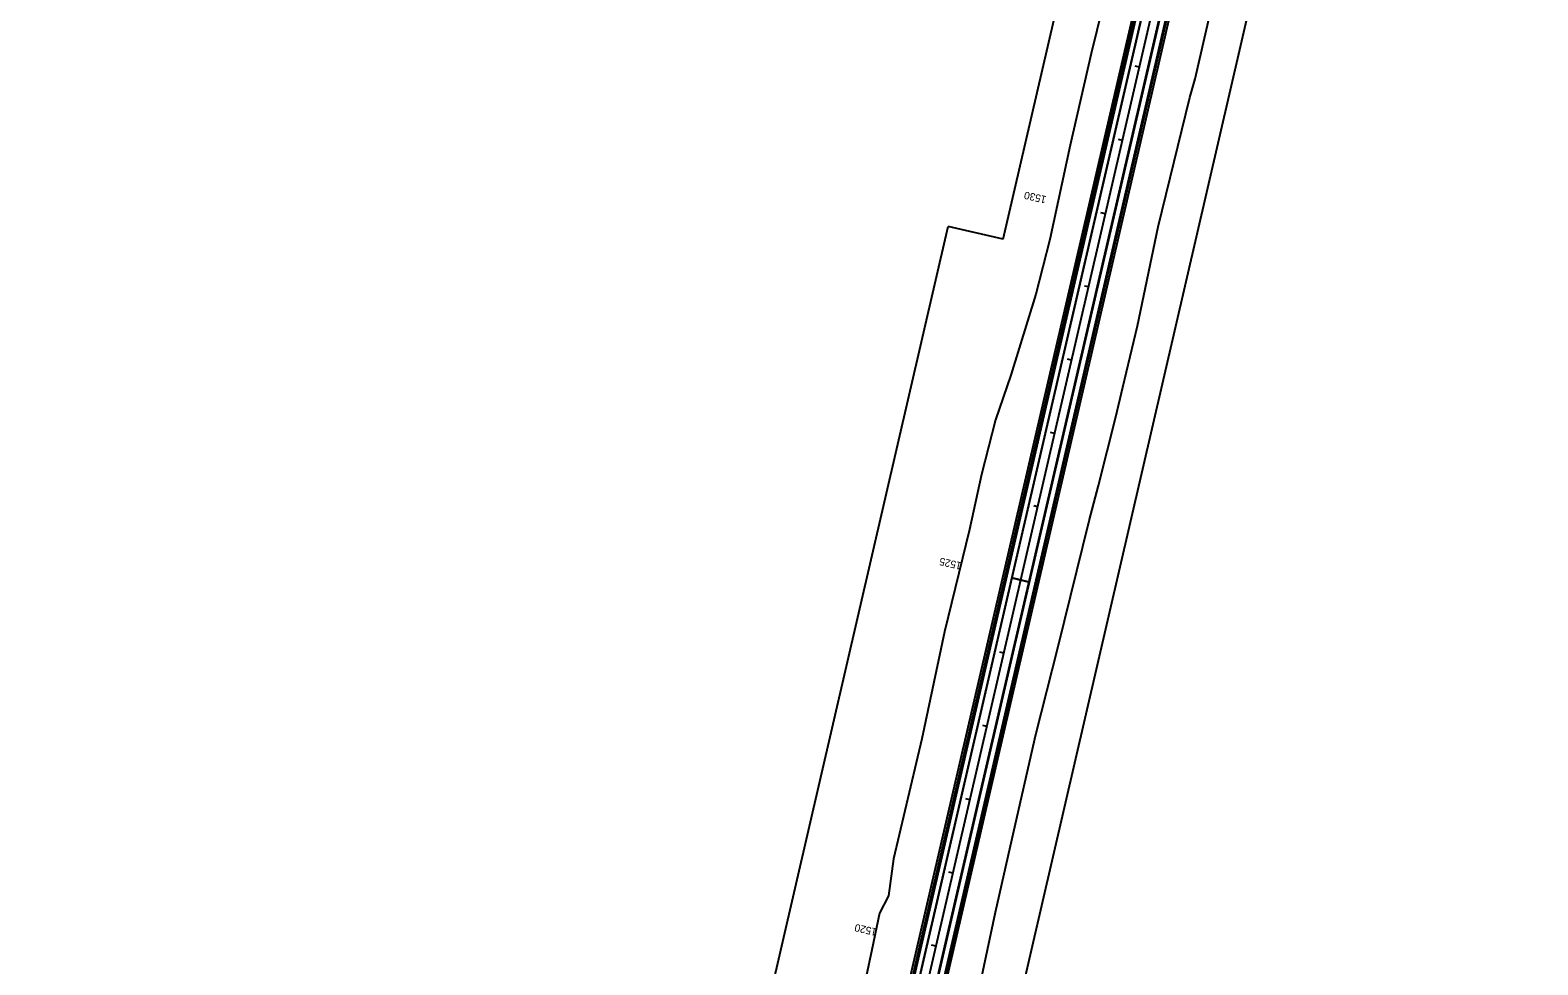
# Model space of a CAD drawing. Extents: x 21596487 to 21601936, y 8263704 to 8275922.
# Drawn here: x 21596705 to 21598711, y 8272284 to 8273528 of the extents above; entities that cross this region are included whole.
import ezdxf

# ---------------------------------------------------------------- set-up
doc = ezdxf.new("R2010")
doc.units = 0
for name, color, linetype in [('Default', 7, 'Continuous'), ('dsnGroundLineIntercept', 7, 'Continuous'), ('dsnPaintPlaceBrokenCenterLineYellow', 7, 'Continuous'), ('dsnPaintPlaceDottedLineYellow', 7, 'Continuous'), ('dsnXsROWLabelLineExist', 7, 'Continuous'), ('EdgeUnpaved', 7, 'Continuous'), ('ErosionControl', 7, 'Continuous'), ('Joints', 7, 'Continuous'), ('TC_DNC', 7, 'Continuous'), ('TC_GranularBackFill', 7, 'Continuous'), ('TC_MacadamStone', 7, 'Continuous'), ('TC_SpecialBackfill', 7, 'Continuous'), ('Wall', 7, 'Continuous')]:
    doc.layers.add(name, color=color, linetype=linetype)

msp = doc.modelspace()

# ---------------------------------------------------------------- linework, layer by layer
at = {"layer": 'Default'}
msp.add_line((21596728.7, 8267202.6), (21598588.8, 8275242.6), dxfattribs=at)
msp.add_line((21596728.7, 8267202.6), (21598588.8, 8275242.6), dxfattribs=at)
at = {"layer": 'dsnGroundLineIntercept'}
for points in [[(21598139.5, 8273590.4), (21598116.6, 8273496.3), (21598088.5, 8273374.5), (21598061.6, 8273249.2), (21598043, 8273176.5), (21598009.5, 8273068.8), (21597989.3, 8273009.3), (21597970.6, 8272936.6), (21597954.5, 8272863.4), (21597921.6, 8272727.4), (21597891.3, 8272584.9), (21597853.5, 8272425.2), (21597846.8, 8272376), (21597834.8, 8272352.9), (21597824.8, 8272304.1), (21597817.4, 8272268.9)], [(21597681.7, 8270993.6), (21597702.8, 8271125.4), (21597722.2, 8271201.3), (21597743.1, 8271302.5), (21597770.5, 8271418.5), (21597788.4, 8271497.6), (21597808, 8271578), (21597843.3, 8271734.3), (21597877.2, 8271880.3), (21597915.6, 8272040.5), (21597945.4, 8272147.9), (21597989.1, 8272354.3), (21598011.6, 8272452.4), (21598042.8, 8272590.9), (21598072.4, 8272707.8), (21598113.7, 8272875.1), (21598126.3, 8272921.7), (21598149.1, 8273013.3), (21598158.8, 8273052.7), (21598177.9, 8273134.5), (21598205.6, 8273266.1), (21598247.8, 8273437.8), (21598254.9, 8273463), (21598281, 8273577.1)]]:
    msp.add_lwpolyline(points, dxfattribs=at)
at = {"layer": 'dsnPaintPlaceBrokenCenterLineYellow'}
msp.add_line((21597006.2, 8268402), (21598343, 8274180.5), dxfattribs=at)
at = {"layer": 'dsnPaintPlaceDottedLineYellow'}
for p, q in [((21596717, 8267205.3), (21598523, 8275011.8)), ((21596739.7, 8267200), (21598545.7, 8275006.6))]:
    msp.add_line(p, q, dxfattribs=at)
at = {"layer": 'dsnXsROWLabelLineExist'}
for p, q in [((21597999.4, 8273249.7), (21598467, 8275270.8)), ((21596850.5, 8267174.4), (21598710.5, 8275214.5)), ((21597413.5, 8271049.8), (21597926.3, 8273266.6)), ((21597999.4, 8273249.7), (21597926.3, 8273266.6))]:
    msp.add_line(p, q, dxfattribs=at)
at = {"layer": 'EdgeUnpaved'}
for p, q in [((21596709.9, 8267206.9), (21598472.3, 8274824.9)), ((21596710.4, 8267206.8), (21598472.9, 8274825.4))]:
    msp.add_line(p, q, dxfattribs=at)
at = {"layer": 'ErosionControl'}
for p, q in [((21598180.6, 8273478.2), (21598175.2, 8273479.5)), ((21598158, 8273380.8), (21598152.7, 8273382)), ((21598135.5, 8273283.4), (21598129.5, 8273284.8)), ((21598113, 8273186), (21598107.6, 8273187.2)), ((21598090.4, 8273088.5), (21598085.1, 8273089.8)), ((21598067.9, 8272991.1), (21598062.5, 8272992.3)), ((21598045.3, 8272893.7), (21598040, 8272894.9)), ((21598022.8, 8272796.2), (21598016.8, 8272797.6)), ((21598000.3, 8272698.8), (21597994.9, 8272700.1)), ((21597977.7, 8272601.4), (21597972.4, 8272602.6)), ((21597955.2, 8272504), (21597949.8, 8272505.2)), ((21597932.6, 8272406.5), (21597927.3, 8272407.8)), ((21597910.1, 8272309.1), (21597904.1, 8272310.5))]:
    msp.add_line(p, q, dxfattribs=at)
at = {"layer": 'TC_DNC'}
for p, q in [((21596708, 8267207.3), (21598514, 8275013.9)), ((21596749.4, 8267197.8), (21598555.4, 8275004.4))]:
    msp.add_line(p, q, dxfattribs=at)
at = {"layer": 'TC_GranularBackFill'}
msp.add_line((21596728.7, 8267202.6), (21598588.8, 8275242.6), dxfattribs=at)
at = {"layer": 'TC_MacadamStone'}
for p, q in [((21596709.2, 8267207.1), (21598515.3, 8275013.6)), ((21596748.2, 8267198.1), (21598554.2, 8275004.6))]:
    msp.add_line(p, q, dxfattribs=at)
at = {"layer": 'TC_SpecialBackfill'}
for p, q in [((21598349.2, 8274260.4), (21598011.1, 8272799)), ((21598034.5, 8272793.5), (21598372.6, 8274254.9)), ((21598011.1, 8272799), (21597673, 8271337.5)), ((21597696.4, 8271332.1), (21598034.5, 8272793.5)), ((21598034.5, 8272793.5), (21598011.1, 8272799)), ((21598011.1, 8272799), (21598034.5, 8272793.5))]:
    msp.add_line(p, q, dxfattribs=at)
at = {"layer": 'Wall'}
for p, q in [((21596705.3, 8267208), (21598511.4, 8275014.5)), ((21596752.1, 8267197.2), (21598558.1, 8275003.7))]:
    msp.add_line(p, q, dxfattribs=at)

# ---------------------------------------------------------------- texts
at = {"layer": 'Joints'}
for s, p in [('1530', (21598057.6, 8273306.5)), ('1525', (21597944.9, 8272819.4)), ('1520', (21597832.2, 8272332.3))]:
    msp.add_text(s, height=10, rotation=166.974, dxfattribs=at).set_placement(p)

doc.saveas('drawing.dxf')
